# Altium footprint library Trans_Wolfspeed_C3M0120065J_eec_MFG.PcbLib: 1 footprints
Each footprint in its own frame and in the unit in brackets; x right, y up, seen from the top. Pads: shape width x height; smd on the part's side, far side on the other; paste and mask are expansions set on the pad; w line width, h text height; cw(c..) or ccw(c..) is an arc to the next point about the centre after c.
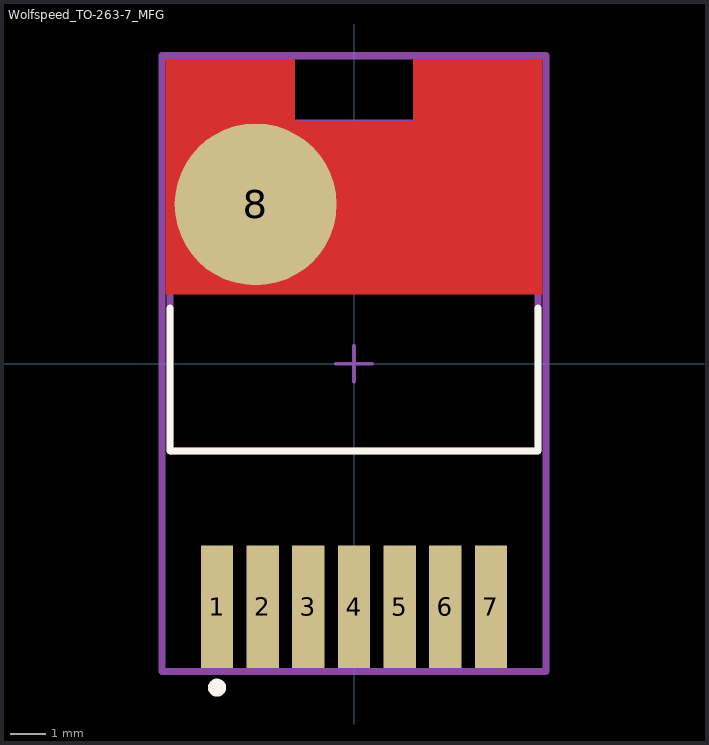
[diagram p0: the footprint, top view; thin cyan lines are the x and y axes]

## Wolfspeed_TO-263-7_MFG [mm]
pads (8):
  rect 0.9x3.4 smd paste+0 mask+0: 1(-3.81,-6.764) 2(-2.54,-6.764) 3(-1.27,-6.764) 4(0,-6.764) 5(1.27,-6.764) 6(2.54,-6.764) 7(3.81,-6.764)
  round 4.505 smd paste+0 mask+0: 8(-2.737,4.429)
Top Layer:
  region: -5.24,1.926 -5.24,8.464 -1.65,8.464 -1.65,6.746 1.65,6.746 1.65,8.464 5.24,8.464 5.24,1.926
Top Overlay:
  circle w0.25: c-3.81,-9.014 r0.125
  lines w0.2: -5.115,1.551 -5.115,-2.429 5.115,-2.429 5.115,1.551
Mechanical 10:
  lines w0.2: -5.34,-8.564 5.34,-8.564 5.34,8.564 -5.34,8.564 -5.34,-8.564
  text ".Designator" at 0,0 h1
Mechanical 12:
  lines w0.2: -5.115,-2.429 5.115,-2.429 5.115,6.696 -5.115,6.696 -5.115,-2.429
Mechanical 15:
  lines w0.1: -0.5,0 0.5,0 ; 0,-0.5 0,0.5
  lines w0.2: -5.34,-8.564 5.34,-8.564 5.34,8.564 -5.34,8.564 -5.34,-8.564
3D body "Trans_Wolfspeed_C3M0120065J_eec.STEP": height 0.25, standoff 0, extent -5.34,-8.564 5.34,8.564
